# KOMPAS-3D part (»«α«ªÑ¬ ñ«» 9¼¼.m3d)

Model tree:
1. Эскиз:1
2. Операция выдавливания:1
     Расстояние 1 = 8
3. Эскиз:2
4. Операция выдавливания:2
     Расстояние 1 = 1
5. Эскиз:3
6. Операция выдавливания:3
     Расстояние 1 = 2.5; Угол 1 = 8
7. Эскиз:4
8. Вырезать элемент выдавливания:1
     Расстояние 1 = 20
9. Эскиз:5
10. Вырезать элемент выдавливания:2
     Расстояние 1 = 3; Угол 1 = 19
11. Скругление:1
     Радиус = 1
12. Скругление:2
     Радиус = 1
13. Скругление:3
     Радиус = 1
14. Эскиз:6
15. Эскиз:7
16. Вырезать элемент выдавливания:3
     Расстояние 2 = 30; Расстояние 1 = 60
17. Эскиз:8
18. Вырезать элемент выдавливания:4
     Расстояние 2 = 30; Расстояние 1 = 60
19. Эскиз:9
20. Операция выдавливания:4
     Расстояние 1 = 10; Расстояние 2 = 62
21. Эскиз:10
22. Вырезать элемент выдавливания:5
     Расстояние 2 = 30; Расстояние 1 = 60
23. Скругление:4
     Радиус = 2
24. Скругление:5
     Радиус = 2
25. Эскиз:11
26. Вырезать элемент выдавливания:6
     Расстояние 1 = 10
27. Эскиз:12
28. Вырезать элемент выдавливания:7
     Расстояние 1 = 2.5; Угол 1 = 3
29. Эскиз:13
30. Вырезать элемент выдавливания:8
     Расстояние 2 = 40; Расстояние 1 = 30
31. Эскиз:14
32. Операция выдавливания:5
     Расстояние 1 = 10
33. Операция выдавливания:6
     Расстояние 1 = 2.5; Расстояние 2 = 5.94316
34. Эскиз:15
35. Вырезать элемент выдавливания:9
     Расстояние 1 = 20
36. Скругление:6
     Радиус = 1
37. Скругление:7
     Радиус = 1
